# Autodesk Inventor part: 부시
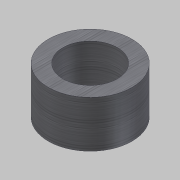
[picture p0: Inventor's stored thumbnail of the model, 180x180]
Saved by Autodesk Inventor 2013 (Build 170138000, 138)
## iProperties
Company: 한국ATC센터
Created: 2014-10
Part Number: 부시
Document SubType Name: Modeling
Designer: 한국ATC센터
Density: 7.86 g/cm^3
Material: 강철, 연강
Mass: 157.788 g
Surface Area: 70.2617 cm^2
Volume: 20.0748 cm^3
Author: KYOUNG IL JANG
Revision Number: 1
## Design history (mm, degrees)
sketch "스케치1"
  geometry: C1 r 21.5 at (0, 0) reference; C2 r 31 at (0, 0) reference; C3 r 14 at (0, 0) reference; 1 further point
  node "참조1"
  node "참조2"
node "작업 평면1"
extrude "돌출1" new body sketch "스케치1" stored distance "d0" = 10; taper "d1" = 0 deg
node "솔리드1"
